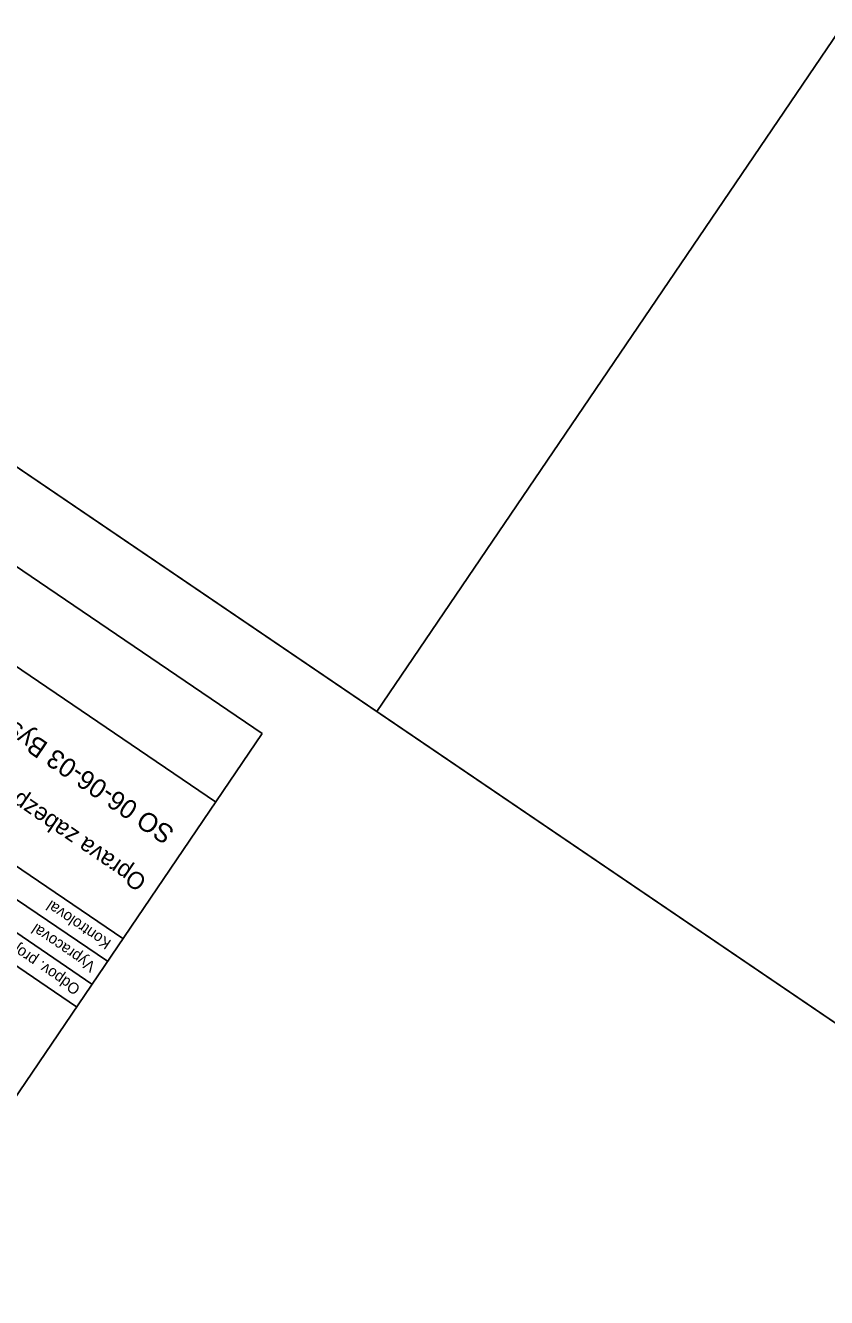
# Model space of a CAD drawing. Extents: x -620624 to -619936, y -1122925 to -1122325.
# Drawn here: x -620485.4 to -620412.7, y -1122560.1 to -1122444.5 of the extents above; entities that cross this region are included whole.
import ezdxf

# ---------------------------------------------------------------- set-up
doc = ezdxf.new("R2010")
doc.units = 0
for name, color, linetype in [('060601_EOV', 7, 'Continuous'), ('060602_NAPÁJENÍ_NN', 7, 'Continuous'), ('060604_ROZVODY_SEE', 7, 'Continuous'), ('POPIS KABELOVÉ TRASY', 7, 'Continuous')]:
    doc.layers.add(name, color=color, linetype=linetype)

msp = doc.modelspace()

# ---------------------------------------------------------------- linework, layer by layer
at = {"layer": '060601_EOV'}
for points in [[(-620456.95, -1122325.02), (-620370.09, -1122384.01), (-620453.52, -1122506.86), (-620540.39, -1122447.87)], [(-620370.09, -1122384.01), (-620283.23, -1122443), (-620366.66, -1122565.85), (-620453.52, -1122506.86)], [(-620540.39, -1122447.87), (-620019.21, -1122801.81), (-620102.64, -1122924.66), (-620623.82, -1122570.71)]]:
    msp.add_lwpolyline(points, close=True, dxfattribs=at)
at = {"layer": 'POPIS KABELOVÉ TRASY'}
for p, q in [((-620463.94, -1122508.85), (-620538.39, -1122458.28)), ((-620468.16, -1122515.05), (-620542.61, -1122464.49)), ((-620476.58, -1122527.46), (-620530.35, -1122490.94)), ((-620477.99, -1122529.53), (-620531.76, -1122493.01)), ((-620479.39, -1122531.6), (-620533.16, -1122495.08)), ((-620480.8, -1122533.67), (-620534.57, -1122497.15)), ((-620463.94, -1122508.85), (-620487.82, -1122544.01))]:
    msp.add_line(p, q, dxfattribs=at)

# ---------------------------------------------------------------- texts
at = {"layer": '060602_NAPÁJENÍ_NN'}
for s, p in [('Odpov. projektant PS, SO, části', (-620480.37, -1122531.84)), ('Kontroloval', (-620477.56, -1122527.7)), ('Vypracoval', (-620478.97, -1122529.77))]:
    msp.add_text(s, height=1, rotation=145.8181, dxfattribs=at).set_placement(p)
at = {"layer": '060604_ROZVODY_SEE'}
for s, height, p in [('SO 06-06-03 Bystřice nad Pernštějnem, úprava rozvodů NN', 1.7296, (-620471.78, -1122517.58)), ('Oprava zabezpečovacího zařízení v ŽST Bystřice nad Pernštejnem', 1.5589, (-620474.31, -1122522))]:
    msp.add_text(s, height=height, rotation=145.8181, dxfattribs=at).set_placement(p)

doc.saveas('drawing.dxf')
